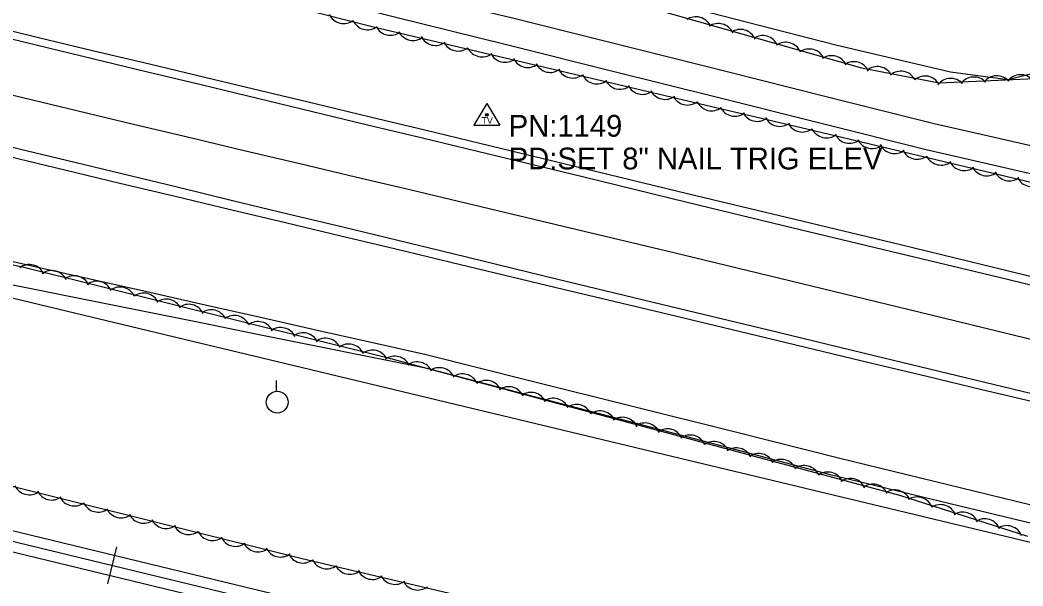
# Model space of a CAD drawing. Extents: x 1441650 to 1491889, y 345904 to 358319.
# Drawn here: x 1453784.4 to 1454014.1, y 352509 to 352638.8 of the extents above; entities that cross this region are included whole.
import ezdxf

# ---------------------------------------------------------------- set-up
doc = ezdxf.new("R2010")
doc.units = 0
for name, color, linetype in [('S_DITCHLINE', 7, 'Continuous'), ('S_EDGE_PAVEMENT', 7, 'Continuous'), ('S_MISC_STRUCTURES', 7, 'Continuous'), ('S_PAVEMENT_CROWN', 7, 'Continuous'), ('S_RAILROAD', 7, 'Continuous'), ('S_SECONDARY_CTL', 7, 'Continuous'), ('S_SECONDARY_CTL_ANNOT', 7, 'Continuous'), ('S_SHOULDER', 7, 'Continuous'), ('S_TREE', 7, 'Continuous'), ('S_UTILITY_POLE', 7, 'Continuous')]:
    doc.layers.add(name, color=color, linetype=linetype)

msp = doc.modelspace()

# ---------------------------------------------------------------- linework, layer by layer
at = {"layer": 'S_DITCHLINE'}
for points in [[(1453772.11, 352669.5), (1453784.75, 352666.22), (1453797.39, 352662.93), (1453809.86, 352659.98), (1453822.34, 352657.02), (1453834.81, 352654.07), (1453847.28, 352651.12), (1453859.76, 352648.17), (1453872.23, 352645.22), (1453884.7, 352642.27), (1453897.17, 352639.31), (1453921.33, 352633.26), (1453945.49, 352627.21), (1453969.65, 352621.15), (1453993.81, 352615.1), (1454006.22, 352612.26), (1454018.63, 352609.42)], [(1453781.92, 352661.32), (1453794.55, 352658.38), (1453807.2, 352655.23), (1453819.86, 352652.08), (1453832.52, 352648.94), (1453845.17, 352645.79), (1453857.83, 352642.64), (1453870.49, 352639.5), (1453883.14, 352636.35), (1453895.8, 352633.2), (1453919.84, 352627.19), (1453943.87, 352621.17), (1453967.91, 352615.16), (1453991.95, 352609.14), (1454004.26, 352606.3), (1454016.57, 352603.45)], [(1453776.11, 352584.95), (1453788.78, 352582.09), (1453801.45, 352579.23), (1453814.11, 352576.37), (1453826.78, 352573.52), (1453839.45, 352570.66), (1453852.12, 352567.8), (1453864.79, 352564.94), (1453877.46, 352562.09), (1453901.06, 352556.17), (1453924.66, 352550.26), (1453948.26, 352544.34), (1453971.85, 352538.42), (1453984.37, 352535.36), (1453996.89, 352532.31), (1454009.41, 352529.25), (1454021.93, 352526.19)], [(1453773.96, 352579.84), (1453786.92, 352577.23), (1453799.88, 352574.63), (1453812.84, 352572.02), (1453825.81, 352569.42), (1453838.77, 352566.81), (1453851.73, 352564.2), (1453864.69, 352561.6), (1453877.65, 352558.99), (1453900.72, 352552.89), (1453923.8, 352546.8), (1453946.87, 352540.7), (1453969.94, 352534.6), (1453982.61, 352531.55), (1453995.27, 352528.49), (1454007.94, 352525.44), (1454020.6, 352522.38)]]:
    msp.add_lwpolyline(points, dxfattribs=at)
at = {"layer": 'S_EDGE_PAVEMENT'}
for points in [[(1453775.8, 352636.1), (1453788.36, 352633.03), (1453800.96, 352629.99), (1453813.57, 352626.96), (1453826.17, 352623.92), (1453838.77, 352620.89), (1453851.37, 352617.85), (1453863.98, 352614.81), (1453876.58, 352611.78), (1453889.18, 352608.74), (1453913.2, 352602.9), (1453937.22, 352597.05), (1453961.46, 352591.18), (1453985.7, 352585.31), (1453998.15, 352582.33), (1454010.6, 352579.35), (1454023.05, 352576.36)], [(1453782.32, 352609.75), (1453795.01, 352606.67), (1453807.7, 352603.6), (1453820.39, 352600.52), (1453833.08, 352597.45), (1453845.7, 352594.4), (1453858.32, 352591.35), (1453870.94, 352588.29), (1453883.56, 352585.24), (1453907.59, 352579.41), (1453931.61, 352573.58), (1453955.82, 352567.73), (1453980.03, 352561.88), (1453992.72, 352558.82), (1454005.4, 352555.75), (1454018.09, 352552.69)]]:
    msp.add_lwpolyline(points, dxfattribs=at)
at = {"layer": 'S_MISC_STRUCTURES'}
msp.add_lwpolyline([(1453516.01, 352752.44), (1453530.34, 352752.03), (1453538.04, 352747.69), (1453551.4, 352736.18), (1453663.7, 352710.09), (1453677.24, 352709.01), (1453711.25, 352713.13), (1453723.82, 352717.45), (1453735.17, 352721.15), (1453744.57, 352716.27), (1453774.53, 352695.59), (1453806.64, 352673.6), (1453818.47, 352669.86), (1453890.35, 352653.96), (1453971.24, 352633.13), (1453997.51, 352626.91), (1454010.66, 352625.16), (1454025.01, 352628.75), (1454033.92, 352639.19), (1454044.46, 352664.99), (1454054.02, 352682.38), (1454066.98, 352697.77), (1454081.51, 352715.08), (1454126.05, 352771.02)], dxfattribs=at)
at = {"layer": 'S_PAVEMENT_CROWN'}
msp.add_lwpolyline([(1453772.51, 352624.06), (1453785.01, 352621.03), (1453797.69, 352617.99), (1453810.38, 352614.96), (1453823.07, 352611.93), (1453835.76, 352608.9), (1453848.5, 352605.88), (1453861.24, 352602.86), (1453873.98, 352599.84), (1453886.72, 352596.82), (1453910.43, 352591.17), (1453934.15, 352585.52), (1453958.44, 352579.61), (1453982.73, 352573.7), (1453995.59, 352570.57), (1454008.45, 352567.45), (1454021.31, 352564.32)], dxfattribs=at)
at = {"layer": 'S_RAILROAD'}
for p, q in [((1453806.46, 352517.98), (1453804.42, 352509.55)), ((1453806, 352516.07), (1453805.99, 352516.04)), ((1453804.89, 352511.5), (1453804.91, 352511.6))]:
    msp.add_line(p, q, dxfattribs=at)
for points in [[(1453358.93, 352624.5), (1454392.41, 352373.86)], [(1453358.37, 352622.19), (1454391.85, 352371.55)], [(1453357.82, 352619.92), (1454391.3, 352369.28)], [(1453805.41, 352513.77), (1453805.44, 352513.77)]]:
    msp.add_lwpolyline(points, dxfattribs=at)
at = {"layer": 'S_SECONDARY_CTL'}
for p, q in [((1453891.33, 352619.66), (1453888.32, 352614.71)), ((1453891.33, 352619.66), (1453894.27, 352614.71)), ((1453888.32, 352614.71), (1453894.27, 352614.71))]:
    msp.add_line(p, q, dxfattribs=at)
for radius in [0.311, 0.183, 0.103]:
    msp.add_circle((1453891.33, 352617.05), radius, dxfattribs=at)
at = {"layer": 'S_SHOULDER'}
for points in [[(1453776.14, 352637.84), (1453788.61, 352634.81), (1453801.32, 352631.77), (1453814.03, 352628.73), (1453826.74, 352625.69), (1453839.45, 352622.65), (1453852.01, 352619.63), (1453864.57, 352616.61), (1453877.14, 352613.59), (1453889.7, 352610.58), (1453913.66, 352604.78), (1453937.62, 352598.99), (1453961.85, 352593.18), (1453986.09, 352587.37), (1453998.59, 352584.31), (1454011.1, 352581.25), (1454023.6, 352578.19)], [(1453781.96, 352607.49), (1453794.62, 352604.46), (1453807.28, 352601.43), (1453819.93, 352598.4), (1453832.59, 352595.37), (1453845.22, 352592.35), (1453857.84, 352589.34), (1453870.47, 352586.32), (1453883.09, 352583.31), (1453907.21, 352577.51), (1453931.33, 352571.71), (1453955.43, 352565.92), (1453979.54, 352560.13), (1453992.14, 352557.11), (1454004.74, 352554.09), (1454017.35, 352551.07)]]:
    msp.add_lwpolyline(points, dxfattribs=at)
at = {"layer": 'S_TREE'}
for points in [[(1453426.54, 352763.86), (1453483.86, 352751.73), (1453526.13, 352749.04), (1453562.4, 352732.47), (1453649.87, 352711.94), (1453668.56, 352707.99), (1453707.3, 352707.17), (1453723.73, 352711.19), (1453738.11, 352718.51), (1453750.3, 352707.98), (1453772.11, 352691.9), (1453800.4, 352671.79), (1453844.86, 352661.11), (1453920.96, 352643.88), (1453977.17, 352627.87), (1453994.91, 352624.39), (1454023.66, 352625.72), (1454034.57, 352633.59), (1454046.81, 352667.77), (1454060.41, 352690.43), (1454077.79, 352698.65), (1454130.66, 352772.29)], [(1454110.3, 352641.36), (1454095.48, 352629.07), (1454088.66, 352620.06), (1454086.33, 352609.09), (1454094.51, 352599.46), (1454118.46, 352593.27), (1454214.16, 352569.41), (1454220.58, 352558.46), (1454215.78, 352549.61), (1454199.35, 352552.83), (1454148.79, 352571.74), (1454081.85, 352585.9), (1453964.92, 352613.73), (1453865.35, 352637.15), (1453749.19, 352666.7), (1453635.25, 352695.04), (1453479.51, 352732.23), (1453403.27, 352752.9)], [(1453415.87, 352666.65), (1453578.35, 352626.33), (1453685.28, 352603.31), (1453784.96, 352582.21), (1453868.41, 352561.4), (1453985.85, 352529.85), (1454015.14, 352520.47)], [(1454092.49, 352503.66), (1454197.68, 352478.65), (1454216.97, 352473.38), (1454219.69, 352463.39), (1454215.69, 352444.49), (1454210.26, 352432.12), (1454192.07, 352431.82), (1454036.6, 352471.08), (1453849.04, 352515.24), (1453729.81, 352544.99), (1453559.38, 352584.91), (1453365.35, 352634.52)], [(1453772.37, 352577.52), (1453784.79, 352574.54), (1453797.2, 352571.56), (1453809.61, 352568.58), (1453822.02, 352565.6), (1453834.43, 352562.62), (1453846.85, 352559.64), (1453859.26, 352556.66), (1453871.67, 352553.68), (1453884.08, 352550.7), (1453896.5, 352547.72), (1453908.91, 352544.74), (1453921.32, 352541.77), (1453933.73, 352538.79), (1453946.15, 352535.81), (1453958.56, 352532.83), (1453970.97, 352529.85), (1453983.38, 352526.87), (1453995.79, 352523.89), (1454008.21, 352520.91), (1454020.62, 352517.93)], [(1453772.37, 352577.52), (1453784.79, 352574.54), (1453797.2, 352571.56), (1453809.61, 352568.58), (1453822.02, 352565.6), (1453834.43, 352562.62), (1453846.85, 352559.64), (1453859.26, 352556.66), (1453871.67, 352553.68), (1453884.08, 352550.7), (1453896.5, 352547.72), (1453908.91, 352544.74), (1453921.32, 352541.77), (1453933.73, 352538.79), (1453946.15, 352535.81), (1453958.56, 352532.83), (1453970.97, 352529.85), (1453983.38, 352526.87), (1453995.79, 352523.89), (1454008.21, 352520.91), (1454020.62, 352517.93)]]:
    msp.add_lwpolyline(points, dxfattribs=at)
for centre, major_axis, ratio, start_param, end_param in [((1453858.53, 352641.63), (3.53, -0.91), 0.999487, 3.827785, 5.600986), ((1453939.21, 352635.91), (-3.13, 1.86), 0.999999, 4.085475, 5.858675), ((1453863.99, 352640.21), (3.53, -0.91), 0.999487, 3.827785, 5.600986), ((1453869.24, 352638.94), (3.64, -0.13), 0.999468, 3.629352, 5.402553), ((1453944.32, 352634.38), (-3.13, 1.86), 0.999999, 4.085475, 5.858675), ((1453874.41, 352637.76), (3.64, -0.13), 0.999468, 3.629352, 5.402553), ((1453949.42, 352633.01), (-3.13, 1.86), 0.999999, 4.085475, 5.858676), ((1453954.53, 352631.59), (-3.13, 1.86), 0.999999, 4.085476, 5.858676), ((1453879.57, 352636.62), (3.64, -0.13), 0.999468, 3.629352, 5.402553), ((1453884.74, 352635.33), (3.64, -0.13), 0.999468, 3.629352, 5.402553), ((1453959.76, 352630.09), (-3.13, 1.86), 0.999999, 4.085476, 5.858676), ((1453890.23, 352634), (3.64, -0.13), 0.999468, 3.629352, 5.402553), ((1453895.53, 352632.75), (3.64, -0.13), 0.999468, 3.629352, 5.402553), ((1453965.18, 352628.51), (-3.13, 1.86), 0.999999, 4.085475, 5.858675), ((1453970.29, 352626.98), (-3.13, 1.86), 0.999999, 4.085475, 5.858675), ((1453900.7, 352631.57), (3.64, -0.13), 0.999468, 3.629352, 5.402553), ((1453905.86, 352630.43), (3.64, -0.13), 0.999468, 3.629352, 5.402553), ((1453975.39, 352625.61), (-3.13, 1.86), 0.999999, 4.085475, 5.858676), ((1453980.8, 352624.48), (-3.58, 0.7), 0.999999, 3.825789, 5.598989), ((1453911.03, 352629.14), (3.64, -0.13), 0.999468, 3.629352, 5.402553), ((1453916.52, 352627.82), (3.64, -0.13), 0.999468, 3.629352, 5.402553), ((1453986.14, 352623.43), (-3.58, 0.7), 0.999999, 3.825789, 5.598989), ((1453991.68, 352622.32), (-3.58, 0.7), 0.999999, 3.825788, 5.598988), ((1454008.16, 352622.38), (-3.64, -0.17), 0.999997, 3.825789, 5.598989), ((1454013.6, 352622.62), (-3.64, -0.17), 0.999997, 3.825789, 5.598989), ((1453921.82, 352626.57), (3.64, -0.13), 0.999468, 3.629352, 5.402553), ((1453926.99, 352625.39), (3.64, -0.13), 0.999468, 3.629352, 5.402553), ((1453997.59, 352621.78), (-3.64, -0.17), 0.999997, 3.825788, 5.598989), ((1454002.87, 352622.1), (-3.64, -0.17), 0.999997, 3.825788, 5.598989), ((1453932.15, 352624.25), (3.64, -0.13), 0.999468, 3.629352, 5.402553), ((1453937.32, 352622.96), (3.64, -0.13), 0.999468, 3.629352, 5.402553), ((1453942.81, 352621.63), (3.64, -0.13), 0.999468, 3.629352, 5.402553), ((1453948.11, 352620.38), (3.64, -0.13), 0.999468, 3.629352, 5.402553), ((1453953.28, 352619.2), (3.64, -0.13), 0.999468, 3.629352, 5.402553), ((1453958.44, 352618.07), (3.64, -0.13), 0.999468, 3.629352, 5.402553), ((1453963.61, 352616.77), (3.64, -0.13), 0.999468, 3.629352, 5.402553), ((1453969.11, 352615.44), (3.55, -0.82), 0.999488, 3.81782, 5.591021), ((1453974.4, 352614.18), (3.55, -0.82), 0.999488, 3.81782, 5.591021), ((1453979.57, 352612.98), (3.55, -0.82), 0.999488, 3.81782, 5.591021), ((1453984.72, 352611.83), (3.55, -0.82), 0.999488, 3.81782, 5.591021), ((1453989.9, 352610.52), (3.55, -0.82), 0.999488, 3.81782, 5.591021), ((1453995.38, 352609.18), (3.55, -0.82), 0.999488, 3.81782, 5.591021), ((1454000.67, 352607.92), (3.55, -0.82), 0.999488, 3.81782, 5.591021), ((1454005.84, 352606.73), (3.55, -0.82), 0.999488, 3.81782, 5.591021), ((1454011, 352605.58), (3.55, -0.82), 0.999488, 3.81782, 5.591021), ((1454016.17, 352604.27), (3.55, -0.82), 0.999488, 3.81782, 5.591021), ((1453786.52, 352579.09), (-3.6, 0.55), 0.998033, 3.73187, 5.505071), ((1453791.67, 352577.72), (-3.6, 0.55), 0.998033, 3.73187, 5.505071), ((1453796.82, 352576.52), (-3.6, 0.55), 0.998033, 3.73187, 5.505071), ((1453801.97, 352575.27), (-3.6, 0.55), 0.998033, 3.73187, 5.505071), ((1453807.25, 352573.95), (-3.6, 0.55), 0.998033, 3.73187, 5.505071), ((1453812.72, 352572.55), (-3.6, 0.55), 0.998033, 3.73187, 5.505071), ((1453817.88, 352571.19), (-3.6, 0.55), 0.998033, 3.73187, 5.505071), ((1453823.02, 352569.98), (-3.6, 0.55), 0.998033, 3.73187, 5.505071), ((1453828.18, 352568.74), (-3.6, 0.55), 0.998033, 3.73187, 5.505071), ((1453833.46, 352567.42), (-3.6, 0.55), 0.998033, 3.73187, 5.505071), ((1453838.93, 352566.02), (-3.6, 0.55), 0.998033, 3.73187, 5.505071), ((1453844.09, 352564.66), (-3.6, 0.55), 0.998033, 3.73187, 5.505071), ((1453849.23, 352563.45), (-3.6, 0.55), 0.998033, 3.73187, 5.505071), ((1453854.38, 352562.2), (-3.6, 0.55), 0.998033, 3.73187, 5.505071), ((1453859.66, 352560.88), (-3.6, 0.55), 0.998033, 3.73187, 5.505071), ((1453865.13, 352559.48), (-3.6, 0.55), 0.998033, 3.73187, 5.505071), ((1453870.23, 352558.09), (-3.52, 0.95), 0.998053, 3.825789, 5.598989), ((1453875.35, 352556.79), (-3.52, 0.95), 0.998053, 3.825789, 5.598989), ((1453880.48, 352555.45), (-3.52, 0.95), 0.998053, 3.825789, 5.598989), ((1453885.74, 352554.03), (-3.52, 0.95), 0.998053, 3.825789, 5.598989), ((1453891.18, 352552.53), (-3.52, 0.95), 0.998053, 3.825789, 5.598989), ((1453896.32, 352551.08), (-3.52, 0.95), 0.998053, 3.825789, 5.598989), ((1453901.44, 352549.78), (-3.52, 0.95), 0.998053, 3.825789, 5.598989), ((1453906.57, 352548.44), (-3.52, 0.95), 0.998053, 3.825789, 5.598989), ((1453911.82, 352547.02), (-3.52, 0.95), 0.998053, 3.825789, 5.598989), ((1453917.27, 352545.53), (-3.52, 0.95), 0.998053, 3.825789, 5.598989), ((1453922.4, 352544.07), (-3.52, 0.95), 0.998053, 3.825789, 5.598989), ((1453927.52, 352542.77), (-3.52, 0.95), 0.998053, 3.825789, 5.598989), ((1453932.65, 352541.43), (-3.52, 0.95), 0.998053, 3.825789, 5.598989), ((1453937.91, 352540.01), (-3.52, 0.95), 0.998053, 3.825789, 5.598989), ((1453943.35, 352538.52), (-3.52, 0.95), 0.998053, 3.825789, 5.598989), ((1453948.48, 352537.06), (-3.52, 0.95), 0.998053, 3.825789, 5.598989), ((1453953.6, 352535.76), (-3.52, 0.95), 0.998053, 3.825789, 5.598989), ((1453958.74, 352534.42), (-3.52, 0.95), 0.998053, 3.825789, 5.598989), ((1453963.99, 352533.01), (-3.52, 0.95), 0.998053, 3.825789, 5.598989), ((1453969.43, 352531.51), (-3.52, 0.95), 0.998053, 3.825789, 5.598989), ((1453786.51, 352533.58), (3.53, -0.88), 0.999978, 3.825789, 5.598989), ((1453974.57, 352530.05), (-3.52, 0.95), 0.998053, 3.825789, 5.598989), ((1453979.69, 352528.75), (-3.52, 0.95), 0.998053, 3.825789, 5.598989), ((1453791.66, 352532.38), (3.53, -0.88), 0.999978, 3.825789, 5.598989), ((1453796.81, 352531.01), (3.53, -0.88), 0.999978, 3.825789, 5.598989), ((1453984.82, 352527.41), (-3.52, 0.95), 0.998053, 3.825789, 5.598989), ((1453989.89, 352525.8), (-3.47, 1.11), 0.998063, 3.825789, 5.598989), ((1453802.28, 352529.61), (3.53, -0.88), 0.999978, 3.825789, 5.598989), ((1453995.25, 352524.05), (-3.47, 1.11), 0.998063, 3.825789, 5.598989), ((1453807.56, 352528.29), (3.53, -0.88), 0.999978, 3.825789, 5.598989), ((1453812.72, 352527.04), (3.53, -0.88), 0.999978, 3.825789, 5.598989), ((1454000.31, 352522.35), (-3.47, 1.11), 0.998063, 3.825789, 5.598989), ((1453817.86, 352525.84), (3.53, -0.88), 0.999978, 3.825789, 5.598989), ((1453823.02, 352524.47), (3.53, -0.88), 0.999978, 3.825789, 5.598989), ((1454005.36, 352520.81), (-3.47, 1.11), 0.998063, 3.825789, 5.598989), ((1454010.43, 352519.23), (-3.47, 1.11), 0.998063, 3.825789, 5.598989), ((1453828.49, 352523.07), (3.53, -0.88), 0.999978, 3.825789, 5.598989), ((1453833.77, 352521.75), (3.53, -0.88), 0.999978, 3.825789, 5.598989), ((1453838.92, 352520.5), (3.53, -0.88), 0.999978, 3.825789, 5.598989), ((1453844.06, 352519.3), (3.53, -0.88), 0.999978, 3.825789, 5.598989), ((1453849.22, 352517.93), (3.53, -0.88), 0.999978, 3.825789, 5.598989), ((1453854.68, 352516.61), (3.55, -0.83), 0.999978, 3.825789, 5.598989), ((1453859.97, 352515.36), (3.55, -0.83), 0.999978, 3.825789, 5.598989), ((1453865.14, 352514.18), (3.55, -0.83), 0.999978, 3.825789, 5.598989), ((1453870.3, 352513.04), (3.55, -0.83), 0.999978, 3.825789, 5.598989), ((1453875.48, 352511.75), (3.55, -0.83), 0.999978, 3.825789, 5.598989)]:
    msp.add_ellipse(centre, major_axis=major_axis, ratio=ratio, start_param=start_param, end_param=end_param, dxfattribs=at)
at = {"layer": 'S_UTILITY_POLE'}
msp.add_line((1453843.17, 352553.69), (1453843.17, 352556.17), dxfattribs=at)
msp.add_circle((1453843.31, 352551.17), 2.5, dxfattribs=at)

# ---------------------------------------------------------------- texts
at = {"layer": 'S_SECONDARY_CTL'}
msp.add_text('TV', height=1.5, rotation=360, dxfattribs=at).set_placement((1453890.12, 352615.04))
at = {"layer": 'S_SECONDARY_CTL_ANNOT'}
for s, p in [('PN:1149', (1453896.33, 352612.05)), ('PD:SET 8" NAIL TRIG ELEV', (1453896.33, 352604.55))]:
    msp.add_text(s, height=5, dxfattribs=at).set_placement(p)

doc.saveas('drawing.dxf')
